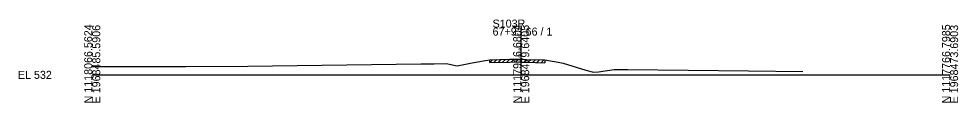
# Model space of a CAD drawing. Extents: x 974 to 1303, y 990 to 10019.
# Drawn here: x 974.3 to 1302.8, y 9990.3 to 10019.4 of the extents above; entities that cross this region are included whole.
import ezdxf

# ---------------------------------------------------------------- set-up
doc = ezdxf.new("R2010")
doc.units = 0
for name, color, linetype in [('Level 10', 7, 'Continuous'), ('Level 60', 7, 'Continuous'), ('Level 61', 7, 'Continuous'), ('Level 63', 7, 'Continuous')]:
    doc.layers.add(name, color=color, linetype=linetype)

msp = doc.modelspace()

# ---------------------------------------------------------------- linework, layer by layer
at = {"layer": 'Level 60'}
for p, q in [((1054.43, 10003.07), (1114.88, 10003.84)), ((1114.88, 10003.84), (1119.53, 10003.83)), ((1119.53, 10003.83), (1123.88, 10003.99)), ((1123.88, 10003.99), (1126.48, 10003.42)), ((1127.59, 10003.13), (1132.3, 10004.03)), ((1132.3, 10004.03), (1134.18, 10004.41)), ((1134.18, 10004.41), (1137.47, 10005.03)), ((1137.47, 10005.03), (1138.99, 10005.29)), ((1138.99, 10005.29), (1146.09, 10005.45)), ((1146.09, 10005.45), (1148.94, 10005.51)), ((1148.94, 10005.51), (1150, 10005.48)), ((1150, 10005.48), (1151.79, 10005.42)), ((1151.79, 10005.42), (1158.3, 10005.2)), ((1158.3, 10005.2), (1162.96, 10004.38)), ((1162.96, 10004.38), (1164.63, 10004.09)), ((1164.63, 10004.09), (1172.66, 10001.66)), ((1000, 10002.92), (1032.73, 10002.9)), ((1032.73, 10002.9), (1054.43, 10003.07)), ((1126.48, 10003.42), (1127.59, 10003.13)), ((1172.66, 10001.66), (1175.25, 10000.96)), ((1175.25, 10000.96), (1177.06, 10001.11)), ((1177.06, 10001.11), (1182.53, 10001.9)), ((1182.53, 10001.9), (1187.33, 10001.89)), ((1187.33, 10001.89), (1229.52, 10001.41)), ((1229.52, 10001.41), (1248.45, 10001.22))]:
    msp.add_line(p, q, dxfattribs=at)
at = {"layer": 'Level 61'}
for p, q in [((1138.99, 10004.29), (1140.02, 10005.31)), ((1138.99, 10004.29), (1138.99, 10005.29)), ((1138.99, 10004.29), (1146.09, 10004.45)), ((1138.99, 10004.29), (1138.99, 10004.29)), ((1140.49, 10004.32), (1141.52, 10005.35)), ((1141.99, 10004.36), (1143.02, 10005.38)), ((1143.49, 10004.39), (1144.52, 10005.42)), ((1144.99, 10004.43), (1146.02, 10005.45)), ((1146.09, 10004.45), (1148.94, 10004.51)), ((1146.49, 10004.46), (1147.51, 10005.48)), ((1147.99, 10004.49), (1149.01, 10005.51)), ((1148.94, 10004.51), (1150, 10004.48)), ((1149.49, 10004.5), (1150.46, 10005.46)), ((1150, 10004.48), (1151.79, 10004.42)), ((1150.99, 10004.45), (1151.96, 10005.41)), ((1151.79, 10004.42), (1158.3, 10004.2)), ((1152.49, 10004.4), (1153.46, 10005.36)), ((1153.99, 10004.35), (1154.96, 10005.31)), ((1155.49, 10004.3), (1156.46, 10005.26)), ((1156.99, 10004.25), (1157.96, 10005.22)), ((1158.3, 10005.2), (1158.3, 10004.2))]:
    msp.add_line(p, q, dxfattribs=at)
at = {"layer": 'Level 63'}
for p, q in [((1150, 10000), (1150, 10016.54)), ((1000, 10000), (1150, 10000)), ((1150, 10000), (1300, 10000))]:
    msp.add_line(p, q, dxfattribs=at)

# ---------------------------------------------------------------- texts
at = {"layer": 'Level 10'}
msp.add_text('537.48', height=0.9, rotation=90, dxfattribs=at).set_placement((1149.95, 10005.98))
at = {"layer": 'Level 63'}
for s, p in [('N 1118066.5624', (1000, 9990)), ('E 1968485.5906', (1002.8, 9990)), ('N 1117916.6804', (1150, 9990)), ('E 1968479.6405', (1152.8, 9990)), ('N 1117766.7985', (1300, 9990)), ('E 1968473.6903', (1302.8, 9990))]:
    msp.add_text(s, height=2.8, rotation=90, dxfattribs=at).set_placement(p)
for s, p in [('S103R', (1140, 10016.54)), ('67+93.66 / 1', (1140, 10013.74)), ('EL 532', (974, 9998.6))]:
    msp.add_text(s, height=2.8, dxfattribs=at).set_placement(p)

doc.saveas('drawing.dxf')
